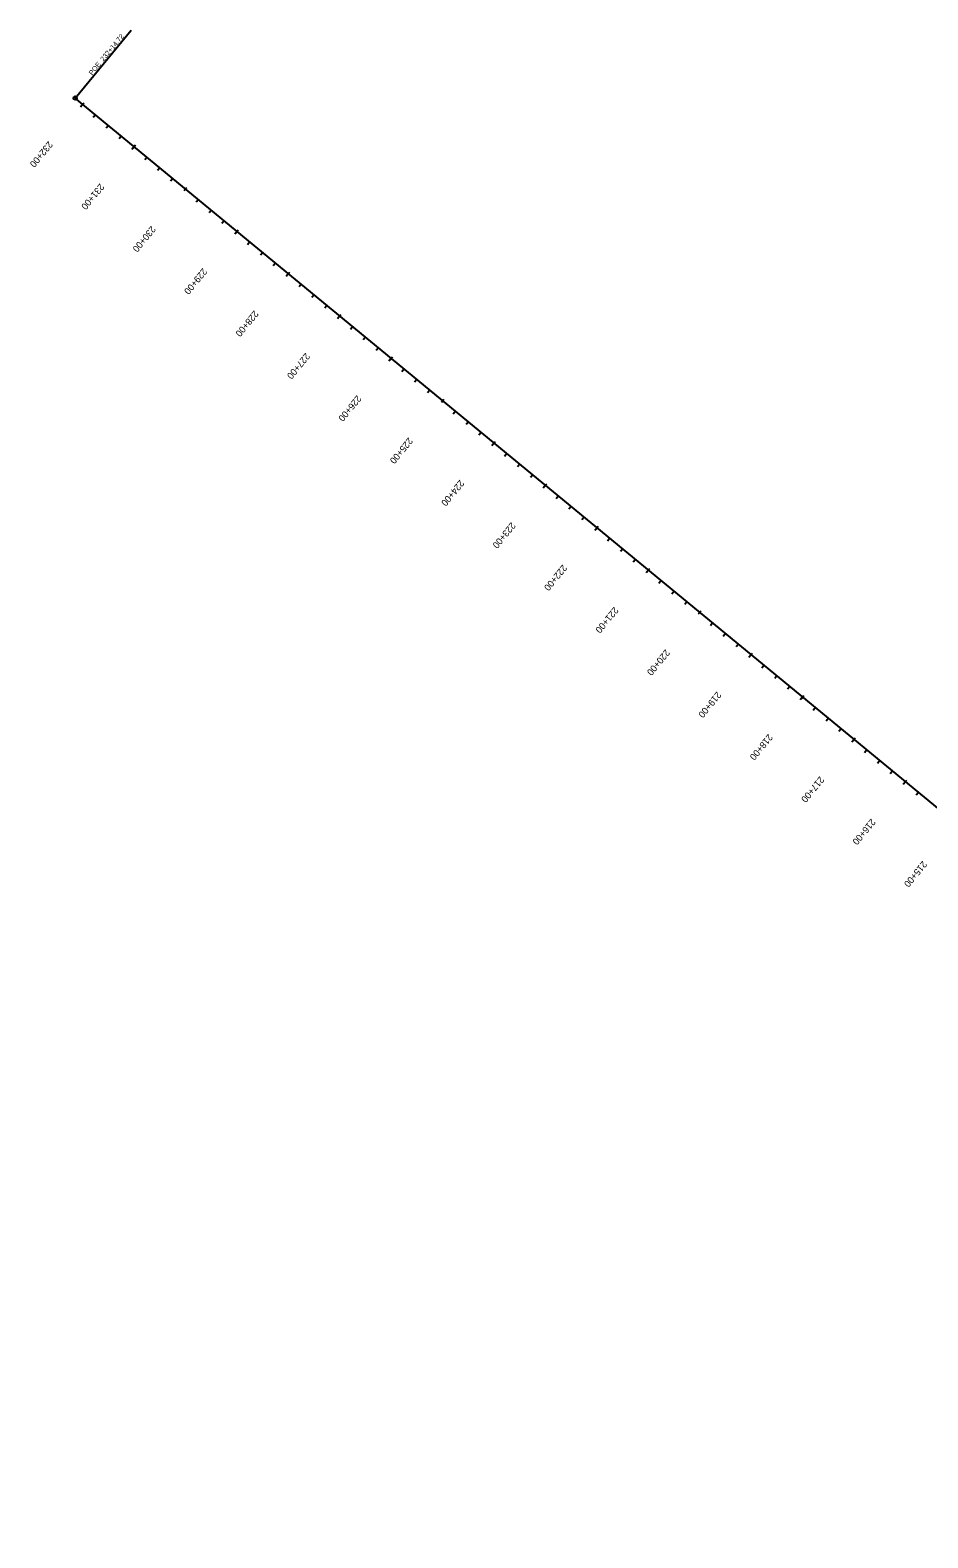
# Model space of a CAD drawing. Extents: x 5226274 to 5237131, y 3641705 to 3648830.
# Drawn here: x 5226274 to 5227622, y 3646566 to 3648830 of the extents above; entities that cross this region are included whole.
import ezdxf

# ---------------------------------------------------------------- set-up
doc = ezdxf.new("R2010")
doc.units = 0
for name, color, linetype in [('Alignment', 7, 'Continuous'), ('TextAlignment', 7, 'Continuous'), ('TextAlignmentLrg', 7, 'Continuous'), ('TextAlignmentSml', 7, 'Continuous')]:
    doc.layers.add(name, color=color, linetype=linetype)

msp = doc.modelspace()

# ---------------------------------------------------------------- linework, layer by layer
at = {"layer": 'Alignment'}
for p in [(5228813, 3646692.7), (5228966.5, 3646566.3)]:
    msp.add_line(p, (5226341.7, 3648728.2), dxfattribs=at)
at = {"layer": 'TextAlignment'}
for p in [(5226341.7, 3648728.2), (5226425.7, 3648830.1)]:
    msp.add_line(p, (5226425.7, 3648830.1), dxfattribs=at)
msp.add_circle((5226341.7, 3648728.2), 2.67, dxfattribs=at)
at = {"layer": 'TextAlignmentLrg'}
for p, q in [((5226353.1, 3648718.9), (5226349.6, 3648714.7)), ((5226430.3, 3648655.3), (5226426.8, 3648651.1)), ((5226505.5, 3648589.4), (5226509.4, 3648594.1)), ((5226584.7, 3648528.1), (5226581.2, 3648523.9)), ((5226661.8, 3648464.6), (5226658.4, 3648460.4)), ((5226739, 3648401), (5226735.6, 3648396.8)), ((5226816.2, 3648337.4), (5226812.7, 3648333.2)), ((5226891.5, 3648271.5), (5226895.3, 3648276.2)), ((5226970.6, 3648210.3), (5226967.1, 3648206)), ((5227047.8, 3648146.7), (5227044.3, 3648142.5)), ((5227125, 3648083.1), (5227121.5, 3648078.9)), ((5227202.2, 3648019.5), (5227198.7, 3648015.3)), ((5227277.4, 3647953.6), (5227281.3, 3647958.3)), ((5227356.5, 3647892.4), (5227353.1, 3647888.2)), ((5227433.7, 3647828.8), (5227430.2, 3647824.6)), ((5227510.9, 3647765.2), (5227507.4, 3647761)), ((5227588.1, 3647701.6), (5227584.6, 3647697.4))]:
    msp.add_line(p, q, dxfattribs=at)
at = {"layer": 'TextAlignmentSml'}
for p, q in [((5226351.1, 3648716.5), (5226355, 3648721.2)), ((5226372.4, 3648703), (5226368.9, 3648698.8)), ((5226391.7, 3648687.1), (5226388.2, 3648682.9)), ((5226411, 3648671.2), (5226407.5, 3648667)), ((5226428.3, 3648652.9), (5226432.2, 3648657.7)), ((5226449.6, 3648639.4), (5226446.1, 3648635.2)), ((5226468.9, 3648623.5), (5226465.4, 3648619.3)), ((5226488.2, 3648607.6), (5226484.7, 3648603.4)), ((5226505.5, 3648589.4), (5226509.4, 3648594.1)), ((5226526.8, 3648575.8), (5226523.3, 3648571.6)), ((5226546.1, 3648559.9), (5226542.6, 3648555.7)), ((5226565.4, 3648544), (5226561.9, 3648539.8)), ((5226582.7, 3648525.8), (5226586.6, 3648530.5)), ((5226604, 3648512.3), (5226600.5, 3648508)), ((5226623.2, 3648496.4), (5226619.8, 3648492.1)), ((5226642.5, 3648480.5), (5226639.1, 3648476.3)), ((5226659.9, 3648462.2), (5226663.8, 3648466.9)), ((5226681.1, 3648448.7), (5226677.7, 3648444.5)), ((5226700.4, 3648432.8), (5226697, 3648428.6)), ((5226719.7, 3648416.9), (5226716.3, 3648412.7)), ((5226737.1, 3648398.6), (5226741, 3648403.4)), ((5226758.3, 3648385.1), (5226754.9, 3648380.9)), ((5226777.6, 3648369.2), (5226774.2, 3648365)), ((5226796.9, 3648353.3), (5226793.4, 3648349.1)), ((5226814.3, 3648335.1), (5226818.2, 3648339.8)), ((5226835.5, 3648321.5), (5226832, 3648317.3)), ((5226854.8, 3648305.6), (5226851.3, 3648301.4)), ((5226874.1, 3648289.7), (5226870.6, 3648285.5)), ((5226891.5, 3648271.5), (5226895.3, 3648276.2)), ((5226912.7, 3648257.9), (5226909.2, 3648253.7)), ((5226932, 3648242.1), (5226928.5, 3648237.8)), ((5226951.3, 3648226.2), (5226947.8, 3648221.9)), ((5226968.6, 3648207.9), (5226972.5, 3648212.6)), ((5226989.9, 3648194.4), (5226986.4, 3648190.2)), ((5227009.2, 3648178.5), (5227005.7, 3648174.3)), ((5227028.5, 3648162.6), (5227025, 3648158.4)), ((5227045.8, 3648144.3), (5227049.7, 3648149)), ((5227067.1, 3648130.8), (5227063.6, 3648126.6)), ((5227086.4, 3648114.9), (5227082.9, 3648110.7)), ((5227105.7, 3648099), (5227102.2, 3648094.8)), ((5227123, 3648080.7), (5227126.9, 3648085.5)), ((5227144.3, 3648067.2), (5227140.8, 3648063)), ((5227163.6, 3648051.3), (5227160.1, 3648047.1)), ((5227182.9, 3648035.4), (5227179.4, 3648031.2)), ((5227200.2, 3648017.2), (5227204.1, 3648021.9)), ((5227221.5, 3648003.6), (5227218, 3647999.4)), ((5227240.7, 3647987.7), (5227237.3, 3647983.5)), ((5227260, 3647971.8), (5227256.6, 3647967.6)), ((5227277.4, 3647953.6), (5227281.3, 3647958.3)), ((5227298.6, 3647940.1), (5227295.2, 3647935.8)), ((5227317.9, 3647924.2), (5227314.5, 3647919.9)), ((5227337.2, 3647908.3), (5227333.8, 3647904.1)), ((5227354.6, 3647890), (5227358.5, 3647894.7)), ((5227375.8, 3647876.5), (5227372.4, 3647872.3)), ((5227395.1, 3647860.6), (5227391.7, 3647856.4)), ((5227414.4, 3647844.7), (5227410.9, 3647840.5)), ((5227431.8, 3647826.4), (5227435.7, 3647831.2)), ((5227453, 3647812.9), (5227449.5, 3647808.7)), ((5227472.3, 3647797), (5227468.8, 3647792.8)), ((5227491.6, 3647781.1), (5227488.1, 3647776.9)), ((5227509, 3647762.9), (5227512.8, 3647767.6)), ((5227530.2, 3647749.3), (5227526.7, 3647745.1)), ((5227549.5, 3647733.4), (5227546, 3647729.2)), ((5227568.8, 3647717.5), (5227565.3, 3647713.3)), ((5227586.1, 3647699.3), (5227590, 3647704)), ((5227607.4, 3647685.7), (5227603.9, 3647681.5))]:
    msp.add_line(p, q, dxfattribs=at)

# ---------------------------------------------------------------- texts
at = {"layer": 'TextAlignment'}
for s, p in [('232+14.72', (5226384.3, 3648782.5)), ('POE ', (5226367.2, 3648761.7))]:
    msp.add_text(s, height=7.5, rotation=50.5226, dxfattribs=at).set_placement(p)
at = {"layer": 'TextAlignmentLrg'}
for s, p in [('230+00', (5226455.9, 3648537)), ('225+00', (5226841.9, 3648219.1)), ('220+00', (5227227.8, 3647901.2)), ('215+00', (5227613.7, 3647583.4))]:
    msp.add_text(s, height=10.02, rotation=230.5226, dxfattribs=at).set_placement(p)
at = {"layer": 'TextAlignmentSml'}
for s, p in [('232+00', (5226301.5, 3648664.2)), ('231+00', (5226378.7, 3648600.6)), ('230+00', (5226455.9, 3648537)), ('229+00', (5226533.1, 3648473.4)), ('228+00', (5226610.3, 3648409.9)), ('227+00', (5226687.5, 3648346.3)), ('226+00', (5226764.7, 3648282.7)), ('225+00', (5226841.9, 3648219.1)), ('224+00', (5226919, 3648155.6)), ('223+00', (5226996.2, 3648092)), ('222+00', (5227073.4, 3648028.4)), ('221+00', (5227150.6, 3647964.8)), ('220+00', (5227227.8, 3647901.2)), ('219+00', (5227305, 3647837.7)), ('218+00', (5227382.2, 3647774.1)), ('217+00', (5227459.4, 3647710.5)), ('216+00', (5227536.5, 3647646.9)), ('215+00', (5227613.7, 3647583.4))]:
    msp.add_text(s, height=10.02, rotation=230.5226, dxfattribs=at).set_placement(p)

doc.saveas('drawing.dxf')
